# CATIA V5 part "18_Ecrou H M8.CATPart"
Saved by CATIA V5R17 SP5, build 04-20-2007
Part number: 18_Ecrou H M8
Definition: Ecrou H M8
Source: Unknown
Bounding box of the stored display mesh (mm): x -6.5 to 6.5, y -7.506 to 7.506, z -6.5 to 0
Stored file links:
  C:\Users\Frédéric\Documents\WF\STSCPI 09-11\Projets\Projet multiplicateur eolienne\Maquette eolienne\18_Ecrou H M8.CATPart
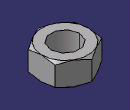
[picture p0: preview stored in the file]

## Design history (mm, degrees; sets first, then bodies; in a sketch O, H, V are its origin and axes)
AxisSystem1: origin (0, 0, 0), X (1, 0, 0), Y (0, 1, 0), Z (0, 0, 1)
Body1 "NONE" (main body)
  Solid1 "Manifold Solid #190": solid without history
